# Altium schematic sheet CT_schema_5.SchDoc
size 259 x 245 mm
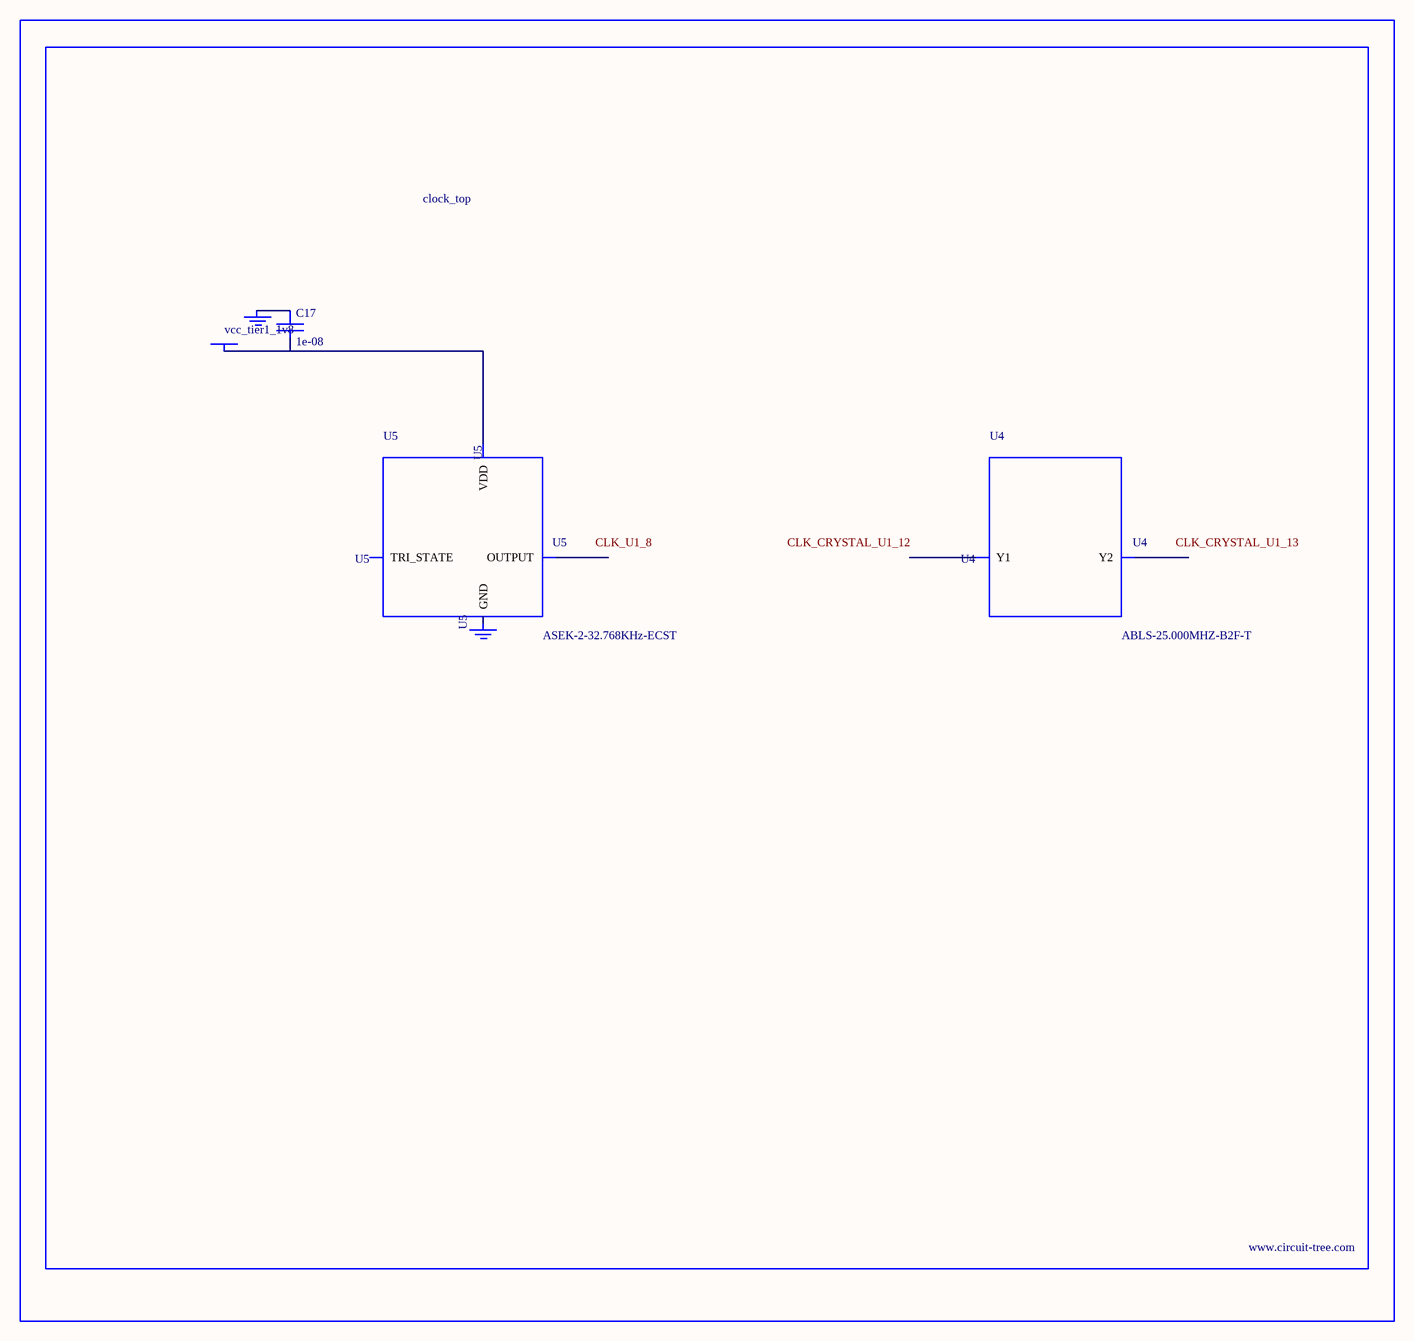
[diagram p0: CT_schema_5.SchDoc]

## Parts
BORDER4  (no value)
C17  1e-08  [C0402]
GND_INSTANCE_4_0  (no value)
GND_INSTANCE_4_1  (no value)
POWER_INSTANCE_4_0  vcc_tier1_1v8
U4  ABLS-25.000MHZ-B2F-T  [ABLS-25.000MHZ-B2F-T]
U5  ASEK-2-32.768KHz-ECST  [ASEK]

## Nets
NetC17_1: C17.1 GND_INSTANCE_4_0.0(GND)
NetC17_2: C17.2 POWER_INSTANCE_4_0.0(PWR) U5.4(VDD)

Not connected (* = marked no-connect by the designer): GND_INSTANCE_4_1 0(GND); U4 1(Y1) 2(Y2); U5 1(TRI_STATE) 2(GND) 3(OUTPUT)

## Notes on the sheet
- Labels drawn without touching a wire or pin: CLK_CRYSTAL_U1_12, CLK_CRYSTAL_U1_13, CLK_U1_8

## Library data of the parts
BORDER4 = BORDER_PAGE4
C17 = C0402C103K3RAC
GND_INSTANCE_4_0 GND_INSTANCE_4_1 = GND
POWER_INSTANCE_4_0 = PWR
